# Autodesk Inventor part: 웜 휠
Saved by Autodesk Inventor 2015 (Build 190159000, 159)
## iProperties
Created: 2025-06
Part Number: 웜 휠
Material: 일반
Document SubType Name: Modeling
Designer: 104
Density: 1 g/cm^3
Appearance: 기본값
Author: 104
Author: jhkim
Creation Date: 2025-05-23
Sending System: Autodesk Inventor 2026
Preprocessor: ST-DEVELOPER v20.1
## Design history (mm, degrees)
node "웜 휠1"
body "Solid1"
node "기준1"
